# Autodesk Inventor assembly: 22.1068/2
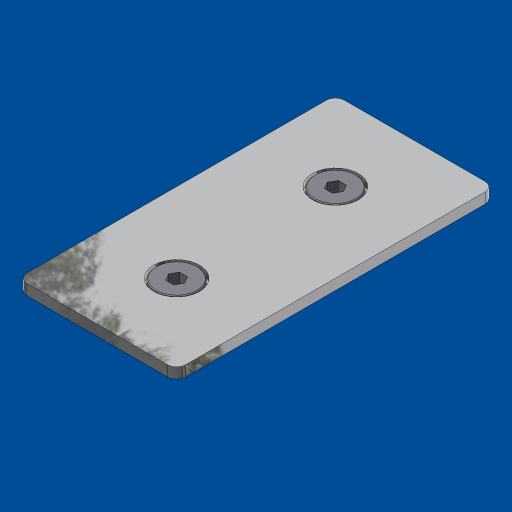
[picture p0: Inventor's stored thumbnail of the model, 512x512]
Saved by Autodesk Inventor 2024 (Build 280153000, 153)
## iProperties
Created: 2012-11
Part Number: 22.1068/2
Document SubType Name: Assembly
Designer: Administrator
Description: END CAP 45X90 AL
Mass: 40.8432 g
Surface Area: 100.661 cm^2
Volume: 12.7413 cm^3
Density: 3.20556 g/cm^3
Author: Administrator
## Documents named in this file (4)
- L:\INVENTOR LIBRARIES\PARTS LIBRARY\END CAPS\22.1068_2 END CAP 45X90 AL.iam
- 22.1068/2 END CAP 45X90 AL.iam
- L:\INVENTOR LIBRARIES\PARTS LIBRARY\END CAPS\SUBCOMPONENTS\22.1068_7 END CAP 45X90 AL.ipt
- L:\INVENTOR LIBRARIES\PARTS LIBRARY\FASTENING ELEMENTS\SCREWS CAP STAINLESS\21.1666 M8x10 Stainless.ipt
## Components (3 placed, 2 different names)
1. 22.1068_7 END CAP 45X90 AL:1 — Insert:1, Insert:2
2. 21.1666 M8x10 Stainless:1 — Insert:1
3. 21.1666 M8x10 Stainless:2 — Insert:2
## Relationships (2: Insert 2)
- Insert:1: 22.1068_7 END CAP 45X90 AL:1 ↔ 21.1666 M8x10 Stainless:1
- Insert:2: 22.1068_7 END CAP 45X90 AL:1 ↔ 21.1666 M8x10 Stainless:2
